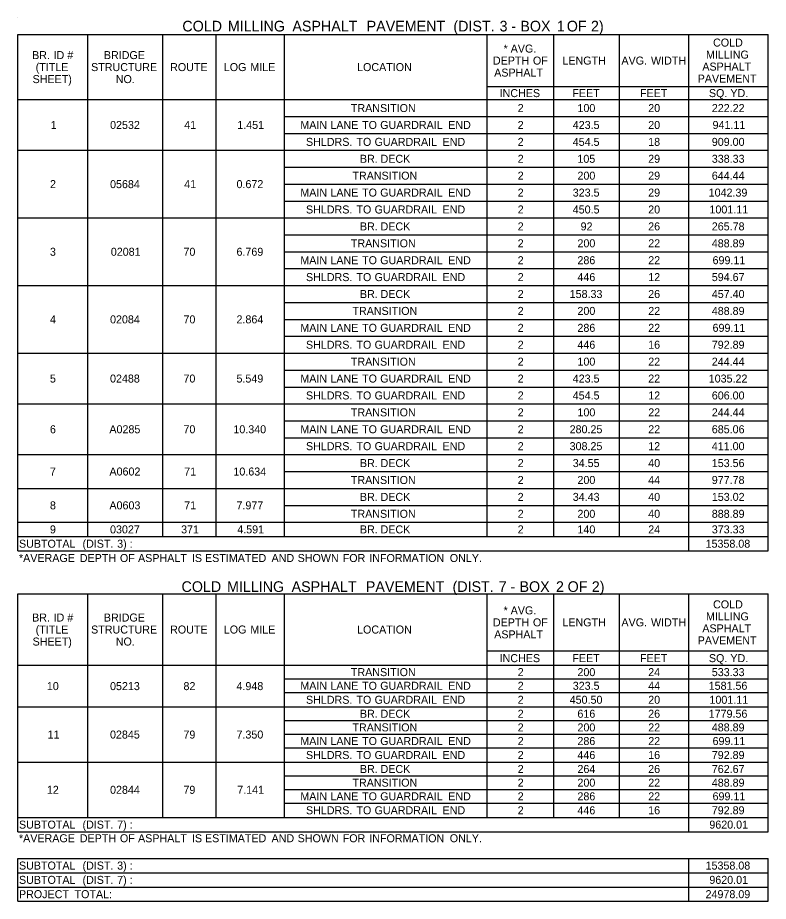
# Model space of a CAD drawing. Extents: x 544478 to 1930787, y -1948294 to 596640.
# Drawn here: x 556430 to 556993, y -1946839 to -1946177 of the extents above; entities that cross this region are included whole.
import ezdxf

# ---------------------------------------------------------------- set-up
doc = ezdxf.new("R2010")
doc.units = 0
doc.layers.add('Default', color=7, linetype='Continuous')

msp = doc.modelspace()

# ---------------------------------------------------------------- linework, layer by layer
at = {"layer": 'Default'}
for p, q in [((556430.1, -1946176.97), (556430.1, -1946176.97)), ((556430.1, -1946189.64), (556992.67, -1946189.64)), ((556430.1, -1946576.72), (556430.1, -1946189.64)), ((556482.75, -1946565.99), (556482.75, -1946189.64)), ((556538.81, -1946565.99), (556538.81, -1946189.64)), ((556578.78, -1946565.99), (556578.78, -1946189.64)), ((556629.97, -1946565.99), (556629.97, -1946189.64)), ((556782.07, -1946565.99), (556782.07, -1946189.64)), ((556831.8, -1946565.99), (556831.8, -1946189.64)), ((556881.03, -1946565.99), (556881.03, -1946189.64)), ((556933.2, -1946576.72), (556933.2, -1946189.64)), ((556992.67, -1946576.72), (556992.67, -1946189.64)), ((556782.07, -1946228.64), (556881.03, -1946228.64)), ((556782.07, -1946228.64), (556831.8, -1946228.64)), ((556831.8, -1946228.64), (556992.67, -1946228.64)), ((556881.03, -1946565.99), (556881.03, -1946228.64)), ((556430.1, -1946238.39), (556992.67, -1946238.39)), ((556629.97, -1946251.07), (556992.67, -1946251.07)), ((556629.97, -1946263.74), (556992.67, -1946263.74)), ((556629.97, -1946263.74), (556992.67, -1946263.74)), ((556430.1, -1946276.42), (556992.67, -1946276.42)), ((556430.1, -1946276.42), (556482.75, -1946276.42)), ((556629.97, -1946289.09), (556992.67, -1946289.09)), ((556629.97, -1946301.77), (556992.67, -1946301.77)), ((556629.97, -1946314.44), (556992.67, -1946314.44)), ((556629.97, -1946314.44), (556992.67, -1946314.44)), ((556430.1, -1946327.12), (556992.67, -1946327.12)), ((556629.97, -1946339.79), (556992.67, -1946339.79)), ((556629.97, -1946352.47), (556992.67, -1946352.47)), ((556629.97, -1946365.14), (556992.67, -1946365.14)), ((556629.97, -1946365.14), (556992.67, -1946365.14)), ((556430.1, -1946377.82), (556992.67, -1946377.82)), ((556430.1, -1946377.82), (556482.75, -1946377.82)), ((556629.97, -1946390.49), (556992.67, -1946390.49)), ((556629.97, -1946403.17), (556992.67, -1946403.17)), ((556629.97, -1946415.84), (556992.67, -1946415.84)), ((556629.97, -1946415.84), (556992.67, -1946415.84)), ((556430.1, -1946428.52), (556992.67, -1946428.52)), ((556430.1, -1946428.52), (556482.75, -1946428.52)), ((556629.97, -1946441.19), (556992.67, -1946441.19)), ((556629.97, -1946453.87), (556992.67, -1946453.87)), ((556629.97, -1946453.87), (556992.67, -1946453.87)), ((556430.1, -1946466.54), (556992.67, -1946466.54)), ((556430.1, -1946466.54), (556482.75, -1946466.54)), ((556629.97, -1946466.54), (556782.07, -1946466.54)), ((556782.07, -1946466.54), (556992.67, -1946466.54)), ((556629.97, -1946479.22), (556992.67, -1946479.22)), ((556629.97, -1946491.89), (556992.67, -1946491.89)), ((556629.97, -1946491.89), (556992.67, -1946491.89)), ((556430.1, -1946504.57), (556992.67, -1946504.57)), ((556629.97, -1946517.24), (556992.67, -1946517.24)), ((556430.1, -1946529.92), (556992.67, -1946529.92)), ((556629.97, -1946542.59), (556992.67, -1946542.59)), ((556430.1, -1946555.27), (556992.67, -1946555.27)), ((556430.1, -1946565.99), (556933.2, -1946565.99)), ((556629.97, -1946565.99), (556992.67, -1946565.99)), ((556430.1, -1946576.72), (556992.67, -1946576.72)), ((556430.1, -1946608.89), (556992.67, -1946608.89)), ((556430.1, -1946787.32), (556430.1, -1946608.89)), ((556482.75, -1946776.59), (556482.75, -1946608.89)), ((556538.81, -1946776.59), (556538.81, -1946608.89)), ((556578.78, -1946776.59), (556578.78, -1946608.89)), ((556629.97, -1946776.59), (556629.97, -1946608.89)), ((556782.07, -1946776.59), (556782.07, -1946608.89)), ((556831.8, -1946776.59), (556831.8, -1946608.89)), ((556881.03, -1946776.59), (556881.03, -1946608.89)), ((556933.2, -1946787.32), (556933.2, -1946608.89)), ((556992.67, -1946787.32), (556992.67, -1946608.89)), ((556782.07, -1946651.79), (556881.03, -1946651.79)), ((556782.07, -1946651.79), (556831.8, -1946651.79)), ((556831.8, -1946651.79), (556992.67, -1946651.79)), ((556881.03, -1946776.59), (556881.03, -1946651.79)), ((556430.1, -1946662.52), (556992.67, -1946662.52)), ((556430.1, -1946662.52), (556482.75, -1946662.52)), ((556629.97, -1946672.76), (556992.67, -1946672.76)), ((556629.97, -1946682.99), (556992.67, -1946682.99)), ((556629.97, -1946682.99), (556992.67, -1946682.99)), ((556430.1, -1946693.72), (556992.67, -1946693.72)), ((556430.1, -1946693.72), (556482.75, -1946693.72)), ((556629.97, -1946703.96), (556992.67, -1946703.96)), ((556629.97, -1946714.19), (556992.67, -1946714.19)), ((556629.97, -1946724.43), (556992.67, -1946724.43)), ((556629.97, -1946724.43), (556992.67, -1946724.43)), ((556430.1, -1946735.16), (556992.67, -1946735.16)), ((556430.1, -1946735.16), (556482.75, -1946735.16)), ((556629.97, -1946745.39), (556992.67, -1946745.39)), ((556629.97, -1946755.63), (556992.67, -1946755.63)), ((556629.97, -1946765.87), (556992.67, -1946765.87)), ((556629.97, -1946765.87), (556992.67, -1946765.87)), ((556430.1, -1946776.59), (556992.67, -1946776.59)), ((556430.1, -1946787.32), (556992.67, -1946787.32)), ((556430.1, -1946807.31), (556992.67, -1946807.31)), ((556430.1, -1946807.31), (556992.67, -1946807.31)), ((556430.1, -1946839.48), (556430.1, -1946807.31)), ((556933.2, -1946839.48), (556933.2, -1946807.31)), ((556992.67, -1946839.48), (556992.67, -1946807.31)), ((556430.1, -1946818.03), (556992.67, -1946818.03)), ((556430.1, -1946828.76), (556992.67, -1946828.76)), ((556430.1, -1946839.48), (556992.67, -1946839.48))]:
    msp.add_line(p, q, dxfattribs=at)

# ---------------------------------------------------------------- texts
for s, height, p in [('COLD', 8, (556553.52, -1946187.31)), (' MILLING', 8, (556584.63, -1946187.31)), (' ASPHALT', 8, (556633.01, -1946187.31)), (' PAVEMENT', 8, (556688.67, -1946187.31)), (' (DIST.', 8, (556753.66, -1946187.31)), (' 3', 8, (556788.28, -1946187.31)), (' BOX', 8, (556803.86, -1946187.31)), (' 1', 8, (556831.18, -1946187.31)), (' OF', 8, (556838.68, -1946187.31)), (' 2)', 8, (556856.79, -1946187.31)), (' -', 8, (556797.11, -1946187.31)), ('COLD', 6, (556951.26, -1946198.64)), ('BR.', 6, (556440.9, -1946208.02)), (' ID', 6, (556454.76, -1946208.02)), (' #', 6, (556465.05, -1946208.02)), ('BRIDGE', 6, (556494.68, -1946208.02)), ('*', 6, (556794.27, -1946203.14)), (' AVG.', 6, (556797.35, -1946203.14)), ('MILLING', 6, (556945.96, -1946207.64)), ('DEPTH', 6, (556786.26, -1946212.14)), (' OF', 6, (556814.03, -1946212.14)), ('LENGTH', 6, (556838.34, -1946212.14)), ('AVG.', 6, (556882.58, -1946212.14)), (' WIDTH', 6, (556902.5, -1946212.14)), ('(TITLE', 6, (556443.59, -1946217.02)), ('STRUCTURE', 6, (556485.13, -1946217.02)), ('ROUTE', 6, (556544.33, -1946217.02)), ('LOG', 6, (556584.58, -1946217.02)), (' MILE', 6, (556602.24, -1946217.02)), ('LOCATION', 6, (556684.47, -1946217.02)), ('ASPHALT', 6, (556787.22, -1946221.14)), ('ASPHALT', 6, (556943.22, -1946216.64)), ('SHEET)', 6, (556441.27, -1946226.02)), ('NO.', 6, (556503.61, -1946226.02)), ('PAVEMENT', 6, (556939.73, -1946225.64)), ('INCHES', 6, (556791.3, -1946236.52)), ('FEET', 6, (556845.79, -1946236.52)), ('FEET', 6, (556896.49, -1946236.52)), ('SQ.', 6, (556948.14, -1946236.52)), (' YD.', 6, (556962, -1946236.52)), ('TRANSITION', 6, (556679.81, -1946247.73)), ('2', 6, (556804.83, -1946247.73)), ('100', 6, (556849.63, -1946247.73)), ('20', 6, (556902.66, -1946247.73)), ('222.22', 6, (556950.34, -1946247.73)), ('1', 6, (556454.86, -1946260.41)), ('02532', 6, (556499.35, -1946260.41)), ('41', 6, (556554.91, -1946260.41)), ('1.451', 6, (556594.66, -1946260.41)), ('MAIN', 6, (556641.93, -1946260.41)), (' LANE', 6, (556662.21, -1946260.41)), (' TO', 6, (556685.99, -1946260.41)), (' GUARDRAIL', 6, (556699.58, -1946260.41)), (' END', 6, (556750.53, -1946260.41)), ('2', 6, (556804.83, -1946260.41)), ('423.5', 6, (556846.1, -1946260.41)), ('20', 6, (556902.66, -1946260.41)), ('941.11', 6, (556950.89, -1946260.41)), ('SHLDRS.', 6, (556646.16, -1946273.08)), (' TO', 6, (556681.76, -1946273.08)), (' GUARDRAIL', 6, (556695.36, -1946273.08)), (' END', 6, (556746.3, -1946273.08)), ('2', 6, (556804.83, -1946273.08)), ('454.5', 6, (556846.1, -1946273.08)), ('18', 6, (556902.64, -1946273.08)), ('909.00', 6, (556950.32, -1946273.08)), ('BR.', 6, (556686.6, -1946285.76)), (' DECK', 6, (556699.84, -1946285.76)), ('2', 6, (556804.83, -1946285.76)), ('105', 6, (556849.59, -1946285.76)), ('29', 6, (556902.64, -1946285.76)), ('338.33', 6, (556950.31, -1946285.76)), ('TRANSITION', 6, (556680.98, -1946298.43)), ('2', 6, (556804.83, -1946298.43)), ('200', 6, (556849.63, -1946298.43)), ('29', 6, (556902.64, -1946298.43)), ('644.44', 6, (556950.32, -1946298.43)), ('2', 6, (556454.31, -1946304.77)), ('05684', 6, (556499.33, -1946304.77)), ('41', 6, (556554.91, -1946304.77)), ('0.672', 6, (556594.11, -1946304.77)), ('MAIN', 6, (556641.93, -1946311.11)), (' LANE', 6, (556662.21, -1946311.11)), (' TO', 6, (556685.99, -1946311.11)), (' GUARDRAIL', 6, (556699.58, -1946311.11)), (' END', 6, (556750.53, -1946311.11)), ('2', 6, (556804.83, -1946311.11)), ('323.5', 6, (556846.1, -1946311.11)), ('29', 6, (556902.64, -1946311.11)), ('1042.39', 6, (556947.97, -1946311.11)), ('SHLDRS.', 6, (556646.16, -1946323.78)), (' TO', 6, (556681.76, -1946323.78)), (' GUARDRAIL', 6, (556695.36, -1946323.78)), (' END', 6, (556746.3, -1946323.78)), ('2', 6, (556804.83, -1946323.78)), ('450.5', 6, (556846.1, -1946323.78)), ('20', 6, (556902.66, -1946323.78)), ('1001.11', 6, (556948.56, -1946323.78)), ('BR.', 6, (556686.6, -1946336.46)), (' DECK', 6, (556699.84, -1946336.46)), ('2', 6, (556804.83, -1946336.46)), ('92', 6, (556851.98, -1946336.46)), ('26', 6, (556902.64, -1946336.46)), ('265.78', 6, (556950.3, -1946336.46)), ('TRANSITION', 6, (556679.81, -1946349.13)), ('2', 6, (556804.83, -1946349.13)), ('200', 6, (556849.63, -1946349.13)), ('22', 6, (556902.68, -1946349.13)), ('488.89', 6, (556950.3, -1946349.13)), ('3', 6, (556454.28, -1946355.47)), ('02081', 6, (556499.9, -1946355.47)), ('70', 6, (556554.34, -1946355.47)), ('6.769', 6, (556594.08, -1946355.47)), (' TO', 6, (556685.99, -1946361.81)), (' GUARDRAIL', 6, (556699.58, -1946361.81)), ('2', 6, (556804.83, -1946361.81)), ('286', 6, (556849.61, -1946361.81)), ('22', 6, (556902.68, -1946361.81)), ('699.11', 6, (556950.89, -1946361.81)), ('MAIN', 6, (556641.93, -1946361.81)), (' LANE', 6, (556662.21, -1946361.81)), (' END', 6, (556750.53, -1946361.81)), ('SHLDRS.', 6, (556646.16, -1946374.48)), (' TO', 6, (556681.76, -1946374.48)), (' GUARDRAIL', 6, (556695.36, -1946374.48)), (' END', 6, (556746.3, -1946374.48)), ('2', 6, (556804.83, -1946374.48)), ('446', 6, (556849.61, -1946374.48)), ('12', 6, (556902.68, -1946374.48)), ('594.67', 6, (556950.31, -1946374.48)), ('BR.', 6, (556686.6, -1946387.16)), (' DECK', 6, (556699.84, -1946387.16)), ('2', 6, (556804.83, -1946387.16)), ('158.33', 6, (556843.79, -1946387.16)), ('26', 6, (556902.64, -1946387.16)), ('457.40', 6, (556950.32, -1946387.16)), ('TRANSITION', 6, (556680.98, -1946399.83)), ('2', 6, (556804.83, -1946399.83)), ('200', 6, (556849.63, -1946399.83)), ('22', 6, (556902.68, -1946399.83)), ('488.89', 6, (556950.3, -1946399.83)), ('4', 6, (556454.29, -1946406.17)), ('02084', 6, (556499.33, -1946406.17)), ('70', 6, (556554.34, -1946406.17)), ('2.864', 6, (556594.1, -1946406.17)), ('MAIN', 6, (556641.93, -1946412.51)), (' LANE', 6, (556662.21, -1946412.51)), (' TO', 6, (556685.99, -1946412.51)), (' GUARDRAIL', 6, (556699.58, -1946412.51)), (' END', 6, (556750.53, -1946412.51)), ('2', 6, (556804.83, -1946412.51)), ('286', 6, (556849.61, -1946412.51)), ('22', 6, (556902.68, -1946412.51)), ('699.11', 6, (556950.89, -1946412.51)), ('SHLDRS.', 6, (556646.16, -1946425.18)), (' TO', 6, (556681.76, -1946425.18)), (' GUARDRAIL', 6, (556695.36, -1946425.18)), (' END', 6, (556746.3, -1946425.18)), ('2', 6, (556804.83, -1946425.18)), ('446', 6, (556849.61, -1946425.18)), ('16', 6, (556902.64, -1946425.18)), ('792.89', 6, (556950.3, -1946425.18)), ('TRANSITION', 6, (556679.81, -1946437.86)), ('2', 6, (556804.83, -1946437.86)), ('100', 6, (556849.63, -1946437.86)), ('22', 6, (556902.68, -1946437.86)), ('244.44', 6, (556950.32, -1946437.86)), ('5', 6, (556454.26, -1946450.53)), ('02488', 6, (556499.31, -1946450.53)), ('70', 6, (556554.34, -1946450.53)), ('5.549', 6, (556594.08, -1946450.53)), ('MAIN', 6, (556641.93, -1946450.53)), (' LANE', 6, (556662.21, -1946450.53)), (' TO', 6, (556685.99, -1946450.53)), (' GUARDRAIL', 6, (556699.58, -1946450.53)), (' END', 6, (556750.53, -1946450.53)), ('2', 6, (556804.83, -1946450.53)), ('423.5', 6, (556846.1, -1946450.53)), ('22', 6, (556902.68, -1946450.53)), ('1035.22', 6, (556948.01, -1946450.53)), ('SHLDRS.', 6, (556646.16, -1946463.21)), (' TO', 6, (556681.76, -1946463.21)), (' GUARDRAIL', 6, (556695.36, -1946463.21)), (' END', 6, (556746.3, -1946463.21)), ('2', 6, (556804.83, -1946463.21)), ('454.5', 6, (556846.1, -1946463.21)), ('12', 6, (556902.68, -1946463.21)), ('606.00', 6, (556950.32, -1946463.21)), ('TRANSITION', 6, (556679.81, -1946475.88)), ('2', 6, (556804.83, -1946475.88)), ('100', 6, (556849.63, -1946475.88)), ('22', 6, (556902.68, -1946475.88)), ('244.44', 6, (556950.32, -1946475.88)), ('6', 6, (556454.28, -1946488.56)), ('A0285', 6, (556498.83, -1946488.56)), ('70', 6, (556554.34, -1946488.56)), ('10.340', 6, (556591.76, -1946488.56)), ('MAIN', 6, (556641.93, -1946488.56)), (' LANE', 6, (556662.21, -1946488.56)), (' TO', 6, (556685.99, -1946488.56)), (' GUARDRAIL', 6, (556699.58, -1946488.56)), (' END', 6, (556750.53, -1946488.56)), ('2', 6, (556804.83, -1946488.56)), ('280.25', 6, (556843.77, -1946488.56)), ('22', 6, (556902.68, -1946488.56)), ('685.06', 6, (556950.31, -1946488.56)), ('SHLDRS.', 6, (556646.16, -1946501.23)), (' TO', 6, (556681.76, -1946501.23)), (' GUARDRAIL', 6, (556695.36, -1946501.23)), (' END', 6, (556746.3, -1946501.23)), ('2', 6, (556804.83, -1946501.23)), ('308.25', 6, (556843.77, -1946501.23)), ('12', 6, (556902.68, -1946501.23)), ('411.00', 6, (556950.32, -1946501.23)), ('BR.', 6, (556686.6, -1946513.91)), (' DECK', 6, (556699.84, -1946513.91)), ('2', 6, (556804.83, -1946513.91)), ('34.55', 6, (556846.1, -1946513.91)), ('40', 6, (556902.66, -1946513.91)), ('153.56', 6, (556950.31, -1946513.91)), ('7', 6, (556454.28, -1946520.24)), ('A0602', 6, (556498.88, -1946520.24)), ('71', 6, (556554.91, -1946520.24)), ('10.634', 6, (556591.77, -1946520.24)), ('TRANSITION', 6, (556679.81, -1946526.58)), ('2', 6, (556804.83, -1946526.58)), ('200', 6, (556849.63, -1946526.58)), ('44', 6, (556902.66, -1946526.58)), ('977.78', 6, (556950.3, -1946526.58)), ('BR.', 6, (556686.6, -1946539.26)), (' DECK', 6, (556699.84, -1946539.26)), ('2', 6, (556804.83, -1946539.26)), ('34.43', 6, (556846.12, -1946539.26)), ('40', 6, (556902.66, -1946539.26)), ('153.02', 6, (556950.34, -1946539.26)), ('8', 6, (556454.28, -1946545.59)), ('A0603', 6, (556498.85, -1946545.59)), ('71', 6, (556554.91, -1946545.59)), ('7.977', 6, (556594.08, -1946545.59)), ('TRANSITION', 6, (556679.81, -1946551.93)), ('2', 6, (556804.83, -1946551.93)), ('200', 6, (556849.63, -1946551.93)), ('40', 6, (556902.66, -1946551.93)), ('888.89', 6, (556950.3, -1946551.93)), ('9', 6, (556454.28, -1946563.63)), ('03027', 6, (556499.32, -1946563.63)), ('371', 6, (556552.58, -1946563.63)), ('4.591', 6, (556594.66, -1946563.63)), ('BR.', 6, (556686.6, -1946563.63)), (' DECK', 6, (556699.84, -1946563.63)), ('2', 6, (556804.83, -1946563.63)), ('140', 6, (556849.63, -1946563.63)), ('24', 6, (556902.66, -1946563.63)), ('373.33', 6, (556950.31, -1946563.63)), ('SUBTOTAL', 6, (556431.07, -1946574.36)), (' (DIST.', 6, (556476.46, -1946574.36)), (' 3)', 6, (556502.43, -1946574.36)), (' :', 6, (556511.77, -1946574.36)), ('15358.08', 6, (556945.65, -1946574.36)), ('*AVERAGE', 6, (556431.07, -1946585.08)), (' DEPTH', 6, (556474.42, -1946585.08)), (' OF', 6, (556504.49, -1946585.08)), (' ASPHALT', 6, (556518.08, -1946585.08)), (' IS', 6, (556558.45, -1946585.08)), (' ESTIMATED', 6, (556568.26, -1946585.08)), (' AND', 6, (556618.12, -1946585.08)), (' SHOWN', 6, (556637.7, -1946585.08)), (' FOR', 6, (556671.48, -1946585.08)), (' INFORMATION', 6, (556691.39, -1946585.08)), (' ONLY.', 6, (556751.71, -1946585.08)), ('COLD', 8, (556552.9, -1946607.53)), (' MILLING', 8, (556584.01, -1946607.53)), (' ASPHALT', 8, (556632.39, -1946607.53)), (' PAVEMENT', 8, (556688.05, -1946607.53)), (' (DIST.', 8, (556753.04, -1946607.53)), (' 7', 8, (556787.66, -1946607.53)), (' BOX', 8, (556803.23, -1946607.53)), (' 2', 8, (556830.54, -1946607.53)), (' OF', 8, (556839.3, -1946607.53)), (' 2)', 8, (556857.41, -1946607.53)), (' -', 8, (556796.48, -1946607.53)), ('COLD', 6, (556951.26, -1946619.84)), ('*', 6, (556794.27, -1946624.34)), (' AVG.', 6, (556797.35, -1946624.34)), ('BR.', 6, (556440.9, -1946629.71)), (' ID', 6, (556454.76, -1946629.71)), (' #', 6, (556465.05, -1946629.71)), ('BRIDGE', 6, (556494.68, -1946629.71)), ('DEPTH', 6, (556786.26, -1946633.34)), (' OF', 6, (556814.03, -1946633.34)), ('LENGTH', 6, (556838.34, -1946633.34)), ('AVG.', 6, (556882.58, -1946633.34)), (' WIDTH', 6, (556902.5, -1946633.34)), ('MILLING', 6, (556945.96, -1946628.84)), ('(TITLE', 6, (556443.59, -1946638.71)), ('STRUCTURE', 6, (556485.13, -1946638.71)), ('ROUTE', 6, (556544.33, -1946638.71)), ('LOG', 6, (556584.58, -1946638.71)), (' MILE', 6, (556602.24, -1946638.71)), ('LOCATION', 6, (556684.47, -1946638.71)), ('ASPHALT', 6, (556943.22, -1946637.84)), ('ASPHALT', 6, (556787.22, -1946642.34)), ('SHEET)', 6, (556441.27, -1946647.71)), ('NO.', 6, (556503.61, -1946647.71)), ('PAVEMENT', 6, (556939.73, -1946646.84)), ('INCHES', 6, (556791.3, -1946660.16)), ('FEET', 6, (556845.79, -1946660.16)), ('FEET', 6, (556896.49, -1946660.16)), ('SQ.', 6, (556948.14, -1946660.16)), (' YD.', 6, (556962, -1946660.16)), ('TRANSITION', 6, (556679.81, -1946670.64)), ('2', 6, (556804.83, -1946670.64)), ('200', 6, (556849.63, -1946670.64)), ('24', 6, (556902.66, -1946670.64)), ('533.33', 6, (556950.31, -1946670.64)), ('10', 6, (556451.96, -1946681.12)), ('05213', 6, (556499.32, -1946681.12)), ('82', 6, (556554.36, -1946681.12)), ('4.948', 6, (556594.08, -1946681.12)), ('MAIN', 6, (556641.93, -1946680.87)), (' LANE', 6, (556662.21, -1946680.87)), (' TO', 6, (556685.99, -1946680.87)), (' GUARDRAIL', 6, (556699.58, -1946680.87)), (' END', 6, (556750.53, -1946680.87)), ('2', 6, (556804.83, -1946680.87)), ('323.5', 6, (556846.1, -1946680.87)), ('44', 6, (556902.66, -1946680.87)), ('1581.56', 6, (556947.98, -1946680.87)), ('SHLDRS.', 6, (556646.16, -1946691.36)), (' TO', 6, (556681.76, -1946691.36)), (' GUARDRAIL', 6, (556695.36, -1946691.36)), (' END', 6, (556746.3, -1946691.36)), ('2', 6, (556804.83, -1946691.36)), ('450.50', 6, (556843.8, -1946691.36)), ('20', 6, (556902.66, -1946691.36)), ('1001.11', 6, (556948.56, -1946691.36)), ('BR.', 6, (556686.6, -1946701.84)), (' DECK', 6, (556699.84, -1946701.84)), ('2', 6, (556804.83, -1946701.84)), ('616', 6, (556849.61, -1946701.84)), ('26', 6, (556902.64, -1946701.84)), ('1779.56', 6, (556947.98, -1946701.84)), ('TRANSITION', 6, (556680.98, -1946712.07)), ('2', 6, (556804.83, -1946712.07)), ('200', 6, (556849.63, -1946712.07)), ('22', 6, (556902.68, -1946712.07)), ('488.89', 6, (556950.3, -1946712.07)), ('11', 6, (556452.53, -1946717.44)), ('02845', 6, (556499.29, -1946717.44)), ('79', 6, (556554.32, -1946717.44)), ('7.350', 6, (556594.09, -1946717.44)), ('MAIN', 6, (556641.93, -1946722.31)), (' LANE', 6, (556662.21, -1946722.31)), (' TO', 6, (556685.99, -1946722.31)), (' GUARDRAIL', 6, (556699.58, -1946722.31)), (' END', 6, (556750.53, -1946722.31)), ('2', 6, (556804.83, -1946722.31)), ('286', 6, (556849.61, -1946722.31)), ('22', 6, (556902.68, -1946722.31)), ('699.11', 6, (556950.89, -1946722.31)), ('SHLDRS.', 6, (556646.16, -1946732.79)), (' TO', 6, (556681.76, -1946732.79)), (' GUARDRAIL', 6, (556695.36, -1946732.79)), ('2', 6, (556804.83, -1946732.79)), ('446', 6, (556849.61, -1946732.79)), ('16', 6, (556902.64, -1946732.79)), ('792.89', 6, (556950.3, -1946732.79)), (' END', 6, (556746.3, -1946732.79)), ('BR.', 6, (556686.6, -1946743.27)), (' DECK', 6, (556699.84, -1946743.27)), ('2', 6, (556804.83, -1946743.27)), ('264', 6, (556849.63, -1946743.27)), ('26', 6, (556902.64, -1946743.27)), ('762.67', 6, (556950.31, -1946743.27)), ('12', 6, (556451.98, -1946758.87)), ('02844', 6, (556499.33, -1946758.87)), ('79', 6, (556554.32, -1946758.87)), ('7.141', 6, (556594.66, -1946758.87)), ('TRANSITION', 6, (556680.98, -1946753.51)), ('2', 6, (556804.83, -1946753.51)), ('200', 6, (556849.63, -1946753.51)), ('22', 6, (556902.68, -1946753.51)), ('488.89', 6, (556950.3, -1946753.51)), ('MAIN', 6, (556641.93, -1946763.75)), (' LANE', 6, (556662.21, -1946763.75)), (' TO', 6, (556685.99, -1946763.75)), (' GUARDRAIL', 6, (556699.58, -1946763.75)), (' END', 6, (556750.53, -1946763.75)), ('2', 6, (556804.83, -1946763.75)), ('286', 6, (556849.61, -1946763.75)), ('22', 6, (556902.68, -1946763.75)), ('699.11', 6, (556950.89, -1946763.75)), ('SHLDRS.', 6, (556646.16, -1946774.23)), (' TO', 6, (556681.76, -1946774.23)), (' GUARDRAIL', 6, (556695.36, -1946774.23)), (' END', 6, (556746.3, -1946774.23)), ('2', 6, (556804.83, -1946774.23)), ('446', 6, (556849.61, -1946774.23)), ('16', 6, (556902.64, -1946774.23)), ('792.89', 6, (556950.3, -1946774.23)), ('SUBTOTAL', 6, (556431.07, -1946784.96)), (' (DIST.', 6, (556476.46, -1946784.96)), (' 7)', 6, (556502.43, -1946784.96)), ('9620.01', 6, (556948.47, -1946784.96)), (' :', 6, (556511.77, -1946784.96)), ('*AVERAGE', 6, (556431.07, -1946795.19)), (' DEPTH', 6, (556474.42, -1946795.19)), (' OF', 6, (556504.49, -1946795.19)), (' ASPHALT', 6, (556518.08, -1946795.19)), (' IS', 6, (556558.45, -1946795.19)), (' ESTIMATED', 6, (556568.26, -1946795.19)), (' AND', 6, (556618.12, -1946795.19)), (' SHOWN', 6, (556637.7, -1946795.19)), (' FOR', 6, (556671.48, -1946795.19)), (' INFORMATION', 6, (556691.39, -1946795.19)), (' ONLY.', 6, (556751.71, -1946795.19)), ('SUBTOTAL', 6, (556431.07, -1946815.67)), (' (DIST.', 6, (556476.46, -1946815.67)), (' 3)', 6, (556502.43, -1946815.67)), (' :', 6, (556511.77, -1946815.67)), ('15358.08', 6, (556945.65, -1946815.67)), ('SUBTOTAL', 6, (556431.07, -1946826.39)), (' (DIST.', 6, (556476.46, -1946826.39)), (' 7)', 6, (556502.43, -1946826.39)), (' :', 6, (556511.77, -1946826.39)), ('9620.01', 6, (556948.47, -1946826.39)), ('PROJECT', 6, (556431.07, -1946837.12)), (' TOTAL:', 6, (556470.5, -1946837.12)), ('24978.09', 6, (556945.65, -1946837.12))]:
    msp.add_text(s, height=height, dxfattribs=at).set_placement(p)

doc.saveas('drawing.dxf')
